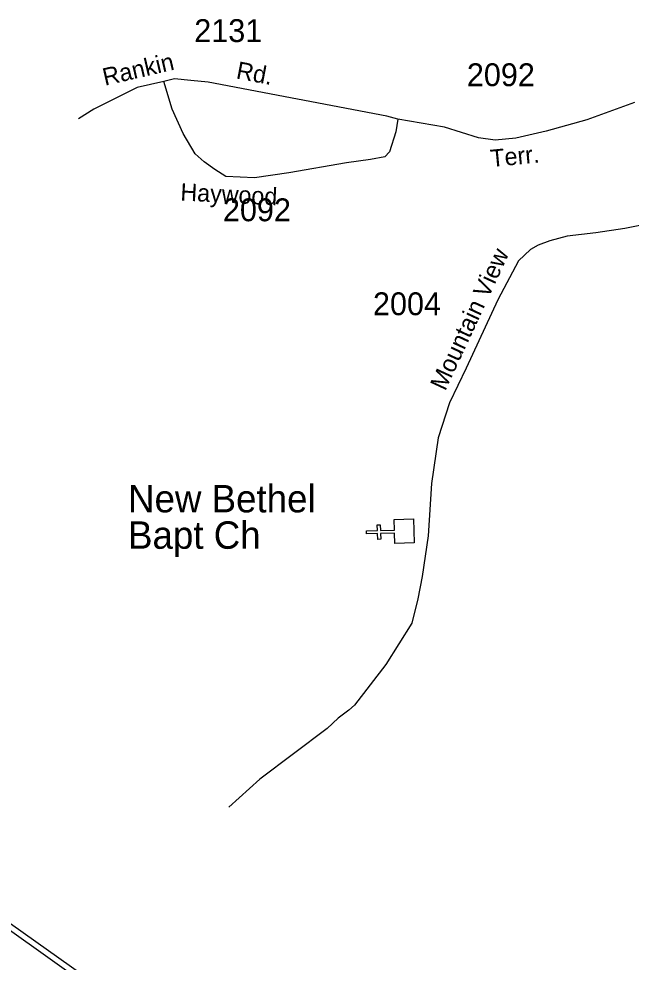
# Model space of a CAD drawing. Extents: x 1364363 to 1407445, y 538563 to 573342.
# Drawn here: x 1376545 to 1379893, y 564968 to 570129 of the extents above; entities that cross this region are included whole.
import ezdxf

# ---------------------------------------------------------------- set-up
doc = ezdxf.new("R2010")
doc.units = 0
for name, color, linetype in [('Exist Cultural Church CELL', 7, 'Continuous'), ('Exist Cultural Church Label', 7, 'Continuous'), ('Exist Hydrographic Buffer Line', 7, 'Continuous'), ('Exist Hydrographic Creek Double Shore', 7, 'Continuous'), ('Exist Road Secondary Type 41 Attributed', 7, 'Continuous'), ('Exist Road Secondary Type 51 Attributed', 7, 'Continuous'), ('Exist Road Secondary Type 51 Label', 7, 'Continuous'), ('Exist Road Secondary Type 51 Number Label', 7, 'Continuous')]:
    doc.layers.add(name, color=color, linetype=linetype)

msp = doc.modelspace()

# ---------------------------------------------------------------- linework, layer by layer
at = {"layer": 'Exist Cultural Church CELL'}
msp.add_lwpolyline([(1378600.6, 567259.1), (1378598.7, 567316), (1378522.6, 567313.6), (1378523.6, 567281.6), (1378507.7, 567281.1), (1378506.7, 567313.1), (1378446.5, 567311.2), (1378446, 567327.2), (1378506.1, 567329.1), (1378505.1, 567361.1), (1378521.1, 567361.6), (1378522.1, 567329.6), (1378598.2, 567332), (1378596.5, 567389.6), (1378702.9, 567393), (1378707, 567262.4)], close=True, dxfattribs=at)
at = {"layer": 'Exist Hydrographic Buffer Line'}
msp.add_lwpolyline([(1377066.8, 564734.5), (1376428.4, 565188.7)], dxfattribs=at)
at = {"layer": 'Exist Hydrographic Creek Double Shore'}
msp.add_lwpolyline([(1377084.7, 564762), (1376443.7, 565218.1)], dxfattribs=at)
at = {"layer": 'Exist Road Secondary Type 41 Attributed'}
msp.add_lwpolyline([(1377338.3, 569787), (1377191.4, 569752.8), (1377076, 569695.1), (1376955.3, 569634.7), (1376871.3, 569582.2)], dxfattribs=at)
at = {"layer": 'Exist Road Secondary Type 51 Attributed'}
for points in [[(1378617.5, 569580.2), (1378556.3, 569596.6), (1377579.7, 569781.7), (1377485.3, 569792.2), (1377396.1, 569800.1), (1377338.3, 569787)], [(1378617.5, 569580.2), (1378606.6, 569511.3), (1378572.5, 569401.1), (1378546.3, 569374.8), (1378467.6, 569359.1), (1378336.4, 569340.7), (1378021.5, 569285.6), (1377834.2, 569259.3), (1377676.8, 569267.2), (1377616.4, 569303.9), (1377558.7, 569345.9), (1377508.9, 569390.6), (1377443.3, 569500.8), (1377382.7, 569634.8), (1377338.3, 569787)], [(1379911.6, 569670.4), (1379651.2, 569576.6), (1379428.4, 569513.7), (1379262.2, 569475.7), (1379149.7, 569464.6), (1379057.7, 569478.2), (1378873.1, 569536.5), (1378617.5, 569580.2)], [(1380120.4, 569035.5), (1379858.3, 568982.8), (1379700.7, 568958.5), (1379543.3, 568940.1), (1379448.5, 568913.7), (1379383.8, 568891), (1379341.9, 568867.4), (1379276.3, 568804.4), (1379163.8, 568591.5), (1378990.6, 568218.7), (1378898.9, 568029.1), (1378838.6, 567837.6), (1378801.9, 567587.1), (1378782.4, 567300.4), (1378750.9, 567077.3), (1378727.3, 566956.5), (1378693.2, 566822.6), (1378551, 566596.3), (1378381, 566373.7), (1378349, 566346.9), (1378291.8, 566302.8), (1378230.9, 566247.2), (1377863.6, 565968.9), (1377693, 565816.6)]]:
    msp.add_lwpolyline(points, dxfattribs=at)

# ---------------------------------------------------------------- texts
at = {"layer": 'Exist Cultural Church Label'}
for s, p in [('New Bethel ', (1377142.1, 567428.9)), ('Bapt Ch', (1377142.1, 567229.7))]:
    msp.add_text(s, height=150, dxfattribs=at).set_placement(p)
at = {"layer": 'Exist Road Secondary Type 51 Label'}
for s, rotation, p in [('Rankin', 13.0766, (1377015.4, 569762.5)), ('Rd.', 349.2656, (1377729.1, 569803.5)), ('Terr.', 5.6576, (1379128.1, 569317.5)), ('Haywood', 357.1359, (1377426.8, 569135.3)), ('Mountain View', 65.0861, (1378876.3, 568089.3))]:
    msp.add_text(s, height=95, rotation=rotation, dxfattribs=at).set_placement(p)
at = {"layer": 'Exist Road Secondary Type 51 Number Label'}
for s, p in [('2131', (1377504.1, 570002)), ('2092', (1378994.7, 569760.6)), ('2092', (1377660.9, 569021.6)), ('2004', (1378481.4, 568507.6))]:
    msp.add_text(s, height=125, dxfattribs=at).set_placement(p)

doc.saveas('drawing.dxf')
